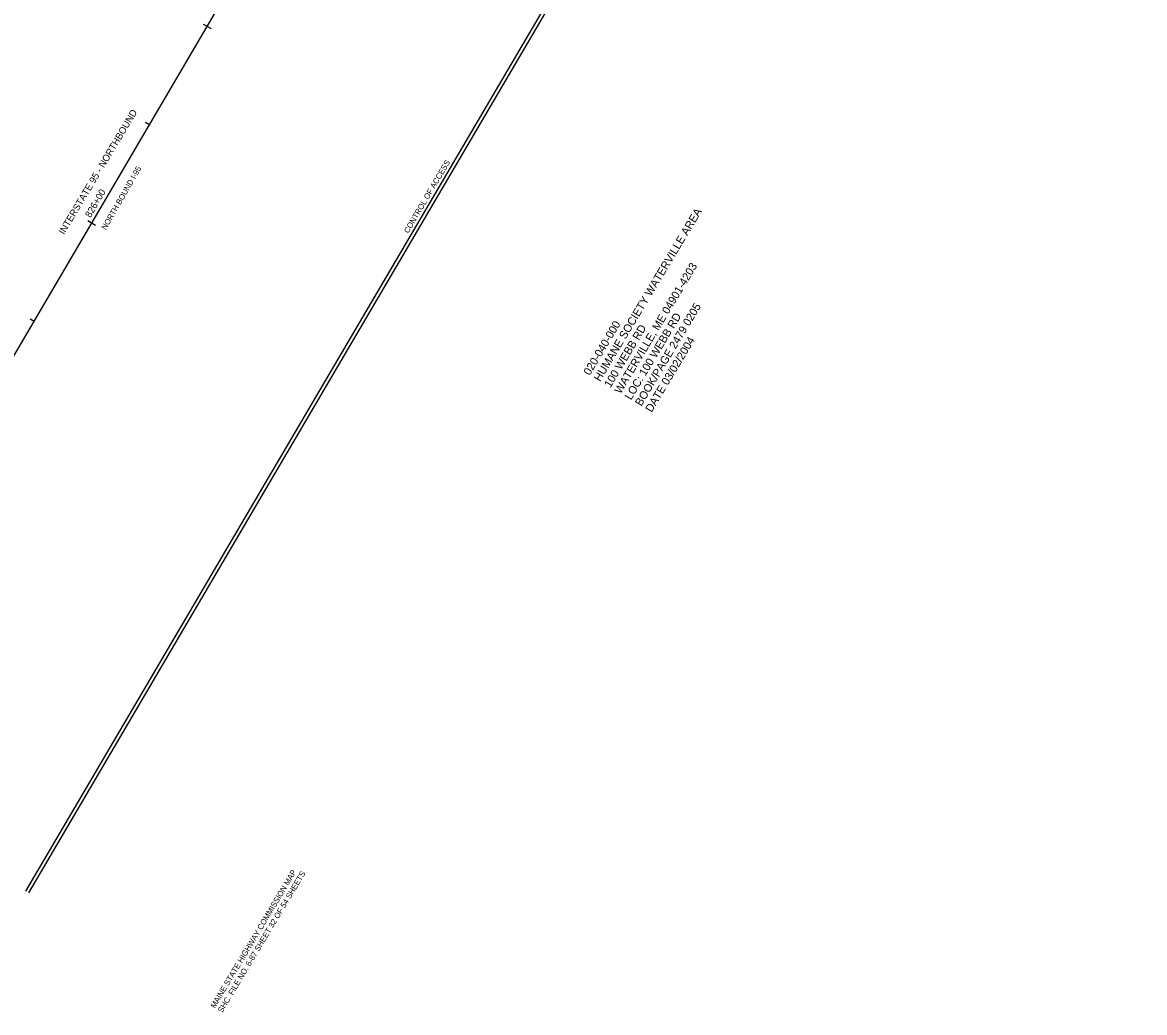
# Model space of a CAD drawing. Extents: x 1160907 to 1161803, y 616778 to 618169.
# Drawn here: x 1161311.2 to 1161803.4, y 616777.9 to 617212.3 of the extents above; entities that cross this region are included whole.
import ezdxf

# ---------------------------------------------------------------- set-up
doc = ezdxf.new("R2010")
doc.units = 0
for name, color, linetype in [('BASE LINE', 7, 'Continuous'), ('BASELN DIST_NTES', 7, 'Continuous'), ('D_Roadway_Centerline', 7, 'Continuous'), ('D_Roadway_Centerline_Text', 7, 'Continuous'), ('E_COA_Line', 7, 'Continuous'), ('E_ROW_Line', 7, 'Continuous'), ('MISCELLN TEXT', 7, 'Continuous'), ('PRP OWNER NAMES', 7, 'Continuous'), ('ROW REFERENCES', 7, 'Continuous')]:
    doc.layers.add(name, color=color, linetype=linetype)

msp = doc.modelspace()

# ---------------------------------------------------------------- linework, layer by layer
at = {"layer": 'BASE LINE'}
msp.add_line((1161206.19, 616893.68), (1161695.52, 617727.46), dxfattribs=at)
at = {"layer": 'D_Roadway_Centerline'}
msp.add_line((1161206.19, 616893.68), (1161695.52, 617727.46), dxfattribs=at)
at = {"layer": 'D_Roadway_Centerline_Text'}
for points in [[(1161390.47, 617211.62), (1161393.92, 617209.6)], [(1161365.16, 617168.5), (1161366.88, 617167.49)], [(1161339.85, 617125.38), (1161343.3, 617123.36)], [(1161314.54, 617082.26), (1161316.27, 617081.25)]]:
    msp.add_lwpolyline(points, dxfattribs=at)
at = {"layer": 'E_COA_Line'}
msp.add_line((1161312.7, 616831.17), (1161802.12, 617665.1), dxfattribs=at)
at = {"layer": 'E_ROW_Line'}
msp.add_line((1161314, 616830.41), (1161803.41, 617664.34), dxfattribs=at)

# ---------------------------------------------------------------- texts
at = {"layer": 'BASELN DIST_NTES'}
msp.add_text('INTERSTATE 95 - NORTHBOUND', height=3, rotation=59.157, dxfattribs=at).set_placement((1161329.46, 617119.02))
at = {"layer": 'D_Roadway_Centerline_Text'}
msp.add_text('826+00', height=3, rotation=59.5921, dxfattribs=at).set_placement((1161341.04, 617126.42))
at = {"layer": 'E_COA_Line'}
msp.add_text('CONTROL OF ACCESS', height=2.49, rotation=59.5921, dxfattribs=at).set_placement((1161480.49, 617119.58))
at = {"layer": 'MISCELLN TEXT'}
msp.add_text('NORTH BOUND I-95', height=2.49, rotation=60.1786, dxfattribs=at).set_placement((1161347.83, 617121.05))
at = {"layer": 'PRP OWNER NAMES'}
for s, p in [('HUMANE SOCIETY WATERVILLE AREA ', (1161564.59, 617054.49)), ('WATERVILLE, ME 04901-4203 ', (1161573.63, 617049.09)), ('BOOK/PAGE 2479 0205 ', (1161582.67, 617043.69)), ('LOC: 100 WEBB RD ', (1161578.15, 617046.39)), ('020-040-000 ', (1161560.07, 617057.19)), ('100 WEBB RD ', (1161569.11, 617051.79)), ('DATE 03/02/2004 ', (1161587.19, 617040.99))]:
    msp.add_text(s, height=3.51, rotation=59.157, dxfattribs=at).set_placement(p)
at = {"layer": 'ROW REFERENCES'}
for s, p in [('MAINE STATE HIGHWAY COMMISSION MAP', (1161395.67, 616779.6)), ('SHC. FILE NO. 6-87 SHEET 32 OF 54 SHEETS', (1161398.89, 616777.67))]:
    msp.add_text(s, height=2.49, rotation=59.157, dxfattribs=at).set_placement(p)

doc.saveas('drawing.dxf')
